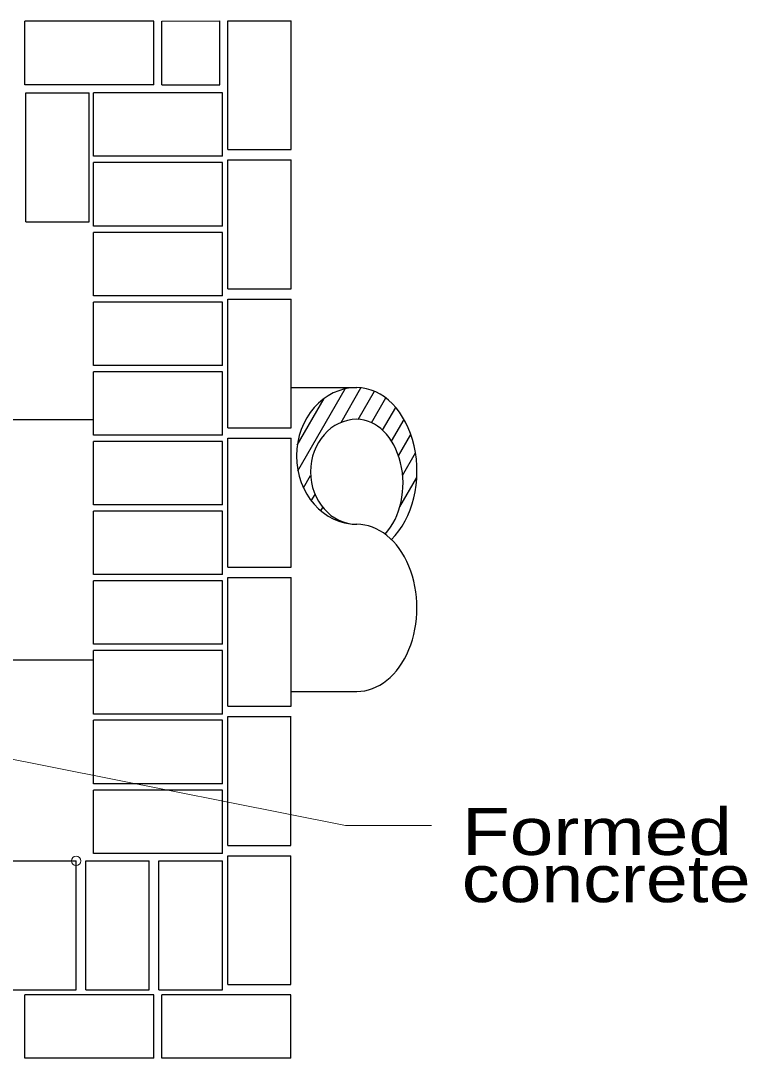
# Model space of a CAD drawing. Extents: x 750.7 to 784.7, y 860.1 to 882.1.
# Drawn here: x 771.324 to 773.802, y 863.094 to 866.633 of the extents above; entities that cross this region are included whole.
import ezdxf

# ---------------------------------------------------------------- set-up
doc = ezdxf.new("R2010")
doc.units = 0
doc.header["$LTSCALE"] = 0.064
doc.header["$PDMODE"] = 32
doc.header["$PDSIZE"] = 0.032
doc.layers.add('1', color=7, linetype='Continuous', lineweight=13)

msp = doc.modelspace()

# ---------------------------------------------------------------- linework, layer by layer
at = {"layer": '1', "lineweight": 25}
for p, q in [((771.77758, 866.63142), (771.338, 866.63142)), ((771.338, 866.41508), (771.338, 866.63142)), ((771.77758, 866.41508), (771.77758, 866.63142)), ((771.8055, 866.63142), (772.00275, 866.63325)), ((771.8055, 866.41508), (771.8055, 866.63142)), ((772.00275, 866.41508), (772.00275, 866.63325)), ((772.03067, 866.63333), (772.24675, 866.63333)), ((772.03067, 866.19375), (772.03067, 866.63325)), ((772.24675, 866.19375), (772.24675, 866.63333)), ((771.77758, 866.41508), (771.338, 866.41508)), ((771.8055, 866.41508), (772.00275, 866.41508)), ((771.34092, 865.94758), (771.34092, 866.38717)), ((771.34092, 866.38717), (771.55717, 866.38717)), ((771.55717, 865.94758), (771.55717, 866.38717)), ((772.01175, 866.38717), (771.57217, 866.38717)), ((771.57217, 866.17092), (771.57217, 866.38717)), ((772.01175, 866.17092), (772.01175, 866.38717)), ((772.03067, 866.19375), (772.24675, 866.19375)), ((772.01175, 866.17092), (771.57217, 866.17092)), ((772.01175, 866.14933), (771.57217, 866.14933)), ((771.57217, 865.93308), (771.57217, 866.14933)), ((772.01175, 865.93308), (772.01175, 866.14933)), ((772.2465, 865.719), (772.2465, 866.15858)), ((771.34092, 865.94758), (771.55717, 865.94758)), ((772.01175, 865.93308), (771.57217, 865.93308)), ((772.01175, 865.9115), (771.57217, 865.9115)), ((771.57217, 865.69525), (771.57217, 865.9115)), ((772.01175, 865.69525), (772.01175, 865.9115)), ((772.01175, 865.69525), (771.57217, 865.69525)), ((772.03067, 865.719), (772.2465, 865.719)), ((772.01175, 865.67375), (771.57217, 865.67375)), ((771.57217, 865.45742), (771.57217, 865.67375)), ((772.01175, 865.45742), (772.01175, 865.67375)), ((772.24625, 865.24433), (772.24625, 865.68383)), ((772.01175, 865.45742), (771.57217, 865.45742)), ((772.01175, 865.43592), (771.57217, 865.43592)), ((771.57217, 865.21958), (771.57217, 865.43592)), ((772.01175, 865.21958), (772.01175, 865.43592)), ((772.24625, 865.38183), (772.46992, 865.38183)), ((772.26942, 865.09825), (772.42983, 865.37733)), ((772.41633, 865.263), (772.48425, 865.38117)), ((772.47467, 865.2735), (772.52983, 865.36942)), ((772.26708, 865.18525), (772.35875, 865.34475)), ((772.52042, 865.26208), (772.56892, 865.3465)), ((772.55792, 865.23633), (772.60267, 865.31425)), ((770.83842, 865.27358), (771.57217, 865.27358)), ((772.58858, 865.19883), (772.63133, 865.27308)), ((772.03067, 865.24433), (772.24625, 865.24433)), ((772.01175, 865.21958), (771.57217, 865.21958)), ((772.01175, 865.19808), (771.57217, 865.19808)), ((771.57217, 864.98175), (771.57217, 865.19808)), ((772.01175, 864.98175), (772.01175, 865.19808)), ((772.246, 864.76958), (772.246, 865.20917)), ((772.61225, 865.149), (772.65433, 865.22217)), ((772.62633, 865.0825), (772.67033, 865.159)), ((772.28817, 865.04), (772.31258, 865.08242)), ((772.61675, 864.97483), (772.67467, 865.07567)), ((772.31492, 864.99558), (772.3275, 865.0175)), ((772.01175, 864.98175), (771.57217, 864.98175)), ((772.01175, 864.96025), (771.57217, 864.96025)), ((771.57217, 864.744), (771.57217, 864.96025)), ((772.01175, 864.744), (772.01175, 864.96025)), ((772.34758, 864.96142), (772.35417, 864.97292)), ((772.03067, 864.76958), (772.246, 864.76958)), ((772.01175, 864.744), (771.57217, 864.744)), ((772.24575, 864.29492), (772.24575, 864.73442)), ((772.01175, 864.72242), (771.57217, 864.72242)), ((771.57217, 864.50617), (771.57217, 864.72242)), ((772.01175, 864.50617), (772.01175, 864.72242)), ((772.01175, 864.50617), (771.57217, 864.50617)), ((772.01175, 864.48467), (771.57217, 864.48458)), ((771.57217, 864.26833), (771.57217, 864.48458)), ((772.01175, 864.26833), (772.01175, 864.48467)), ((770.8935, 864.45367), (771.57217, 864.45367)), ((772.24575, 864.34542), (772.46992, 864.34542)), ((772.03067, 864.29492), (772.24575, 864.29492)), ((772.01175, 864.26833), (771.57217, 864.26833)), ((772.01175, 864.24683), (771.57217, 864.24683)), ((771.57217, 864.0305), (771.57217, 864.24683)), ((772.01175, 864.0305), (772.01175, 864.24683)), ((772.03067, 864.25975), (772.24575, 864.25975)), ((772.01175, 864.0305), (771.57217, 864.0305)), ((772.01175, 864.009), (771.57217, 864.009)), ((772.01175, 864.009), (771.57217, 864.009)), ((771.57217, 863.86492), (771.57217, 864.009)), ((772.01175, 863.93042), (772.01175, 864.009)), ((772.01175, 863.93275), (772.01175, 864.009)), ((772.01175, 863.79267), (772.01175, 863.95517)), ((771.57217, 863.79267), (771.57217, 863.93275)), ((772.01175, 863.79267), (772.01175, 863.88442)), ((772.03067, 863.82017), (772.2455, 863.82017)), ((772.01175, 863.79267), (771.57217, 863.79267)), ((772.01175, 863.79267), (771.57217, 863.79267)), ((772.24525, 863.34542), (772.24525, 863.785)), ((771.29658, 863.76733), (771.51283, 863.76733)), ((771.51283, 863.32775), (771.51283, 863.76733)), ((771.546, 863.32775), (771.546, 863.76733)), ((771.546, 863.76733), (771.76225, 863.76733)), ((771.76225, 863.32775), (771.76225, 863.76733)), ((771.79542, 863.32775), (771.79542, 863.76733)), ((771.79542, 863.76733), (772.01175, 863.76733)), ((772.01175, 863.32775), (772.01175, 863.76733)), ((771.29658, 863.32775), (771.51283, 863.32775)), ((771.546, 863.32775), (771.76225, 863.32775)), ((771.79542, 863.32775), (772.01175, 863.32775)), ((772.03067, 863.34542), (772.24525, 863.34542)), ((771.338, 863.09433), (771.338, 863.3105)), ((772.24508, 863.31025), (771.8055, 863.31025)), ((771.8055, 863.09417), (771.8055, 863.31025)), ((772.24508, 863.094), (772.24508, 863.31025)), ((771.77758, 863.09433), (771.338, 863.09433)), ((772.24508, 863.09417), (771.8055, 863.09417))]:
    msp.add_line(p, q, dxfattribs=at)
for points in [[(772.03067, 865.719), (772.03067, 866.15858), (772.24675, 866.15858)], [(772.03067, 865.24433), (772.03067, 865.68392), (772.2465, 865.68392)], [(772.03067, 864.76958), (772.03067, 865.20917), (772.24625, 865.20917)], [(772.03067, 864.29492), (772.03067, 864.73442), (772.246, 864.73442)], [(772.03067, 863.82017), (772.03067, 863.93183), (772.03067, 864.25975)], [(772.2455, 863.82017), (772.2455, 863.919), (772.2455, 864.25975)], [(772.03067, 863.34542), (772.03067, 863.785), (772.24542, 863.785)], [(771.77758, 863.09417), (771.77758, 863.3105), (771.338, 863.3105)]]:
    msp.add_lwpolyline(points, dxfattribs=at)
at = {"layer": '1'}
msp.add_lwpolyline([(770.44133, 864.28367), (772.43192, 863.8875), (772.72508, 863.8875)], dxfattribs=at)
at = {"layer": '1', "lineweight": 25}
for centre, major_axis, ratio, start_param, end_param in [((772.46991, 865.14866), (0, -0.23319), 0.880667, 3.1415927, 6.2831853), ((772.46991, 865.09684), (0, -0.28501), 0.720546, 0.6125527, 3.1415926), ((772.46991, 865.09454), (0, -0.17907), 0.880667, 3.1415927, 6.2831853), ((772.46991, 865.05475), (0, -0.21887), 0.720546, 0.6602514, 3.1415909), ((772.46991, 864.63046), (0, -0.28501), 0.720546, 6.2831853, 9.424778)]:
    msp.add_ellipse(centre, major_axis=major_axis, ratio=ratio, start_param=start_param, end_param=end_param, dxfattribs=at)
at = {"layer": '1'}
msp.add_point((771.51283, 863.76733), dxfattribs=at)

# ---------------------------------------------------------------- texts
for s, width, p in [('Formed', 1.25, (772.82817, 863.78742)), ('concrete', 1.2, (772.82817, 863.62642))]:
    msp.add_text(s, height=0.16, dxfattribs=dict(at, width=width)).set_placement(p)

doc.saveas('drawing.dxf')
